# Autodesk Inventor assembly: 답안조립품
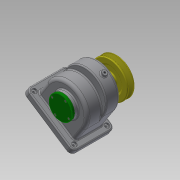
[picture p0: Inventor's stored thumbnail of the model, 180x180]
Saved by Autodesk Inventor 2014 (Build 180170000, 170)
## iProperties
Created: 2017-11
Part Number: 답안조립품
Document SubType Name: Assembly
Designer: user
Author: user
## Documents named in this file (14)
- C:\Users\user\Desktop\471108v1006[1]\답안조립품.iam
- C:\Users\user\Desktop\471108v1006[1]\축.ipt
- C:\Users\user\Desktop\471108v1006[1]\키 - 5 x 5 x 18.ipt
- C:\Users\user\Desktop\471108v1006[1]\V-벨트풀리.ipt
- C:\Users\user\Desktop\471108v1006[1]\멈춤나사 - M4 x 10.ipt
- 멈춤나사 - M4 x 10.ipt
- C:\Users\user\Desktop\471108v1006[1]\베어링 6002.ipt
- C:\Users\user\Desktop\471108v1006[1]\앞커버.ipt
- C:\Users\user\Desktop\471108v1006[1]\오일 실 15 30 7.ipt
- C:\Users\user\Desktop\471108v1006[1]\뒤커버.ipt
- C:\Users\user\Desktop\471108v1006[1]\키 - 6 x 6 x 22.ipt
- C:\Users\user\Desktop\471108v1006[1]\스퍼기어.ipt
- C:\Users\user\Desktop\471108v1006[1]\본체1.ipt
- C:\Users\user\Desktop\471108v1006[1]\볼트 M3 x 8.ipt
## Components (1 placed, 1 different names)
1. V-벨트풀리:1 — 각도:1
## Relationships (1: Angle 1)
- 각도:1 [Angle]: V-벨트풀리:1
